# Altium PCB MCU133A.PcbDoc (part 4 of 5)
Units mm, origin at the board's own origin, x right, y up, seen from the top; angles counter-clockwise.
Board outline 58.42 x 139.7 mm, 4 copper layers (Top Signal, GND, PWR, Bottom Signal), stack 1.565 mm thick; 278 components, 226 nets, 1057 pads, 868 vias.
Unrouted connection lines stored in the file: 237.
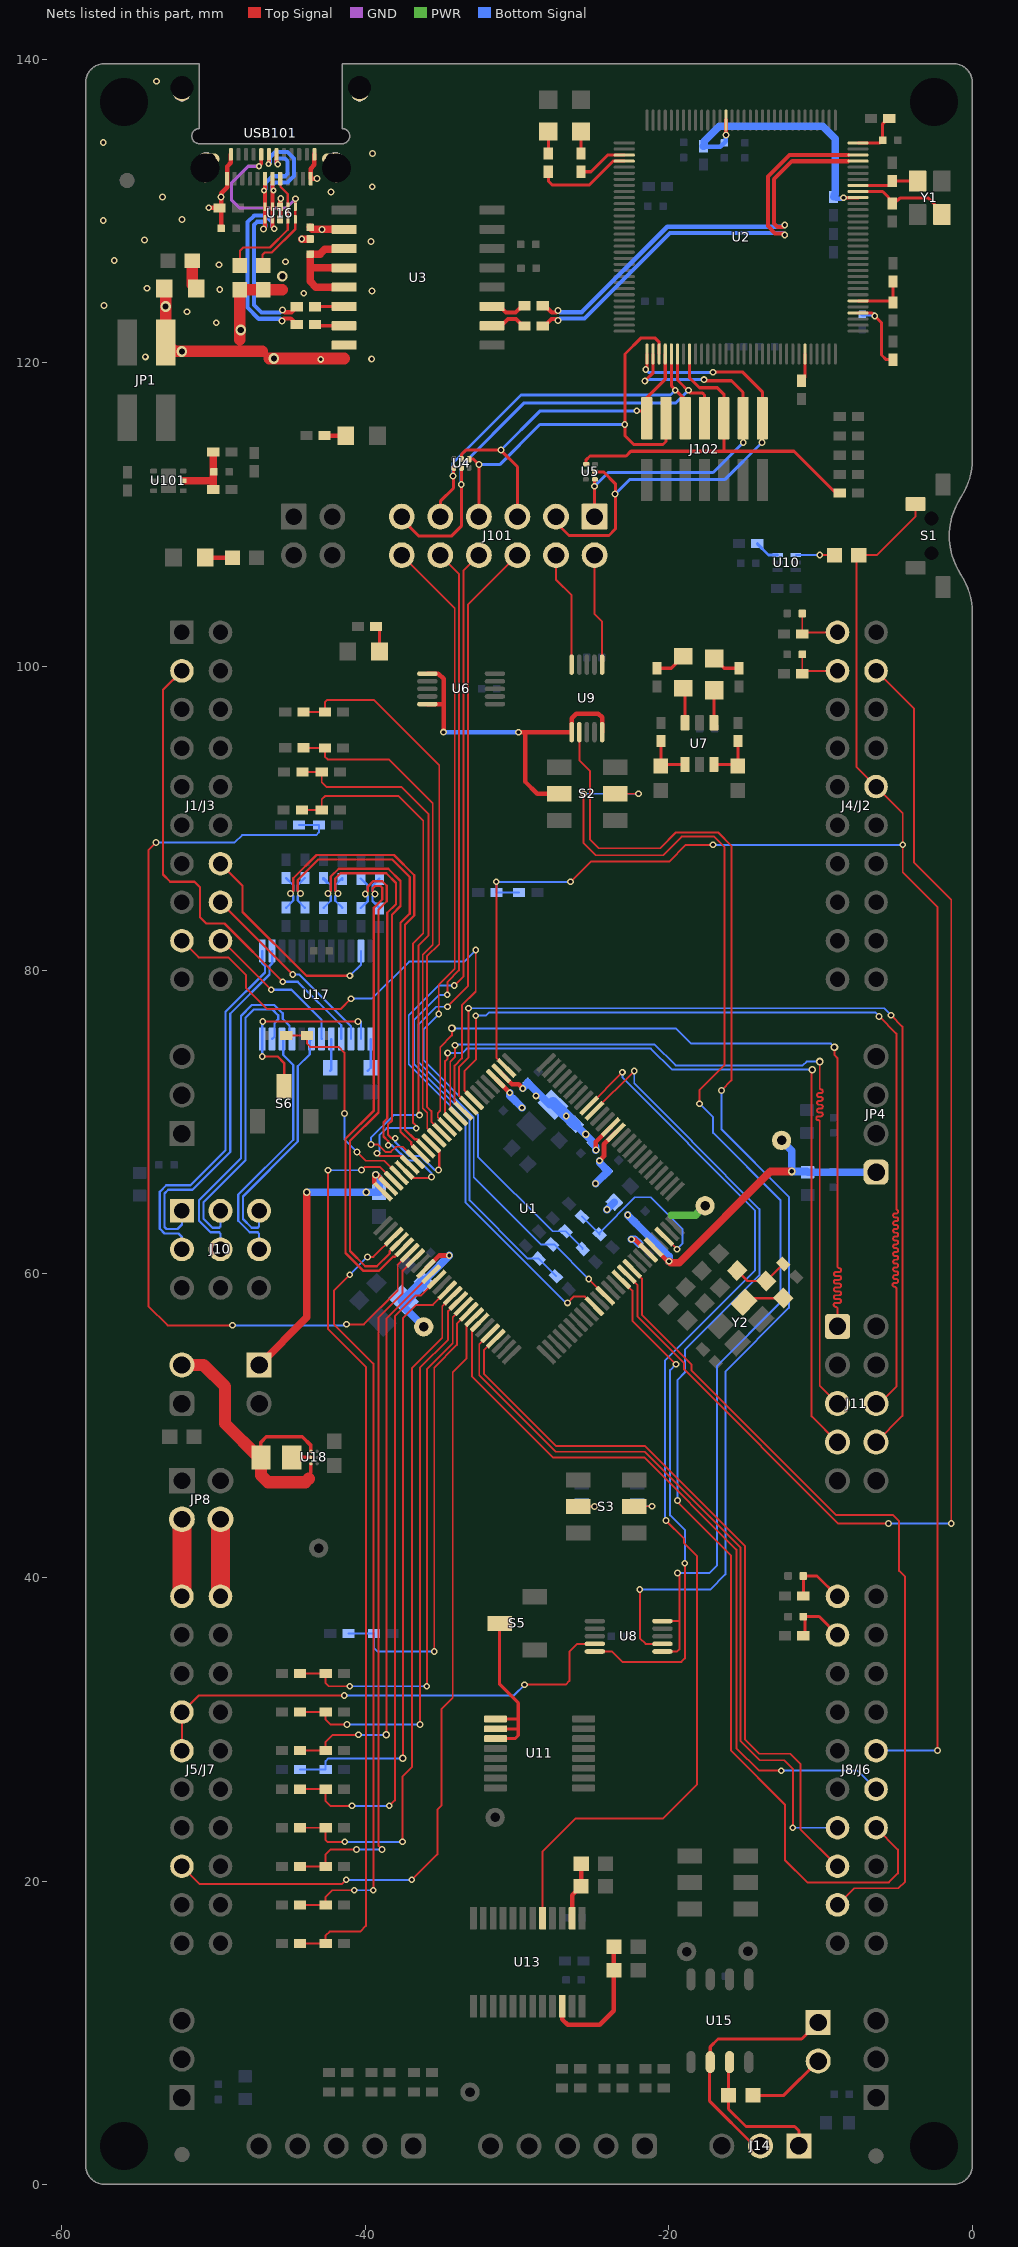
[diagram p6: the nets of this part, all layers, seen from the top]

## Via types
v1: diameter 0.45, hole 0.25, Top Signal to Bottom Signal, tented both sides, 822 vias
v2: diameter 0.5, hole 0.3, Top Signal to Bottom Signal, tented both sides, 22 vias
v3: diameter 0.7, hole 0.4, Top Signal to Bottom Signal, tented both sides, 17 vias
v4: diameter 0.4, hole 0.2, Top Signal to Bottom Signal, tented both sides, 5 vias
v5: diameter 0.5, hole 0.2, Top Signal to Bottom Signal, tented both sides, 2 vias

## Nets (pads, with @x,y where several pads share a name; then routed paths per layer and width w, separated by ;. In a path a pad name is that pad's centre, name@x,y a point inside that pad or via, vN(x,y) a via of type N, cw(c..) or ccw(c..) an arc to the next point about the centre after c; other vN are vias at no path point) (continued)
GPIO49_FSITXD0: J11.6 U1.8 | length 64.1
  Top Signal w0.127: U1.8@-32.818,71.432 -33.447,72.061 -33.447,73.366 -32.715,74.098 v1(-32.715,76.998) ; J11.6@-6.351,51.449 -6.135,51.449 -5.011,52.573 -5.011,59.018 ccw(c-5.138,59.018) -5.138,59.145 cw(c-5.138,59.272) -5.265,59.272 cw(c-5.138,59.272) -5.138,59.399 -5.011,59.399 ccw(c-5.011,59.517) -4.893,59.517 -4.893,59.535 ccw(c-5.011,59.535) -5.011,59.653 -5.1,59.653 cw(c-5.1,59.78) -5.227,59.78 cw(c-5.1,59.78) -5.1,59.907 -5.011,59.907 ccw(c-5.011,60.025) -4.893,60.025 -4.893,60.043 ccw(c-5.011,60.043) -5.011,60.161 -5.1,60.161 cw(c-5.1,60.288) -5.227,60.288 cw(c-5.1,60.288) -5.1,60.415 -5.011,60.415 ccw(c-5.011,60.533) -4.893,60.533 -4.893,60.551 ccw(c-5.011,60.551) -5.011,60.669 -5.1,60.669 cw(c-5.1,60.796) -5.227,60.796 cw(c-5.1,60.796) -5.1,60.923 -5.011,60.923 ccw(c-5.011,61.041) -4.893,61.041 -4.893,61.059 ccw(c-5.011,61.059) -5.011,61.177 -5.1,61.177 cw(c-5.1,61.304) -5.227,61.304 cw(c-5.1,61.304) -5.1,61.431 -5.011,61.431 ccw(c-5.011,61.549) -4.893,61.549 -4.893,61.567 ccw(c-5.011,61.567) -5.011,61.685 -5.1,61.685 cw(c-5.1,61.812) -5.227,61.812 cw(c-5.1,61.812) -5.1,61.939 -5.011,61.939 ccw(c-5.011,62.057) -4.893,62.057 -4.893,62.075 ccw(c-5.011,62.075) -5.011,62.193 -5.1,62.193 cw(c-5.1,62.32) -5.227,62.32 cw(c-5.1,62.32) -5.1,62.447 -5.011,62.447 ccw(c-5.011,62.565) -4.893,62.565 -4.893,62.583 ccw(c-5.011,62.583) -5.011,62.701 -5.1,62.701 cw(c-5.1,62.828) -5.227,62.828 cw(c-5.1,62.828) -5.1,62.955 -5.011,62.955 ccw(c-5.011,63.073) -4.893,63.073 -4.893,63.091 ccw(c-5.011,63.091) -5.011,63.209 -5.1,63.209 cw(c-5.1,63.336) -5.227,63.336 cw(c-5.1,63.336) -5.1,63.463 -5.011,63.463 ccw(c-5.011,63.581) -4.893,63.581 -4.893,63.599 ccw(c-5.011,63.599) -5.011,63.717 -5.1,63.717 cw(c-5.1,63.844) -5.227,63.844 cw(c-5.1,63.844) -5.1,63.971 -5.011,63.971 ccw(c-5.011,64.089) -4.893,64.089 -4.893,64.107 ccw(c-5.011,64.107) -5.011,64.225 -5.011,64.632 -5.011,75.814 v1(-6.148,76.951)
  Bottom Signal w0.127: v1(-32.715,76.998) -32.049,76.998 -31.836,77.211 -6.408,77.211 v1(-6.148,76.951)
GPIO50_FSITXD1: J11.8 U1.9 | length 64.1
  Top Signal w0.127: v1(-33.199,77.488) -33.199,74.232 -33.808,73.622 -33.808,71.715 U1.9@-33.171,71.078 ; J11.8@-6.351,48.909 -4.616,50.644 -4.616,76.282 v1(-5.36,77.027)
  Bottom Signal w0.127: v1(-33.199,77.488) -5.822,77.488 v1(-5.36,77.027)
GPIO51: J1/J3.9 U1.10 | length 34.7
  Top Signal w0.127: J1/J3.9@-52.071,81.929 -50.979,80.837 -49.012,80.837 -47.857,79.682 -47.857,78.833 -46.458,77.433 -41.627,77.433 v1(-40.943,78.117) ; U1.10@-33.525,70.725 -34.116,71.316 -34.116,73.706 -33.637,74.185 -33.637,77.67 -32.716,78.591 v1(-32.716,81.319)
  Bottom Signal w0.127: v1(-40.943,78.117) -39.553,78.117 -37.113,80.557 -33.478,80.557 v1(-32.716,81.319)
GPIO52_FSIRXD0: J11.5 U1.11 | length 55
  Top Signal w0.127: v1(-34.088,75.046) -34.088,74.267 -34.397,73.957 -34.397,70.89 U1.11@-33.878,70.371 ; v2(-10.059,73.979) -10.059,72.245 ccw(c-9.965,72.245) -9.965,72.15 ; -9.986,72.15 cw(c-9.986,72.023) -9.859,72.023 cw(c-9.986,72.023) -9.986,71.896 -10.059,71.896 -10.11,71.896 ccw(c-10.11,71.769) -10.237,71.769 ccw(c-10.11,71.769) -10.11,71.642 -10.059,71.642 -9.986,71.642 cw(c-9.986,71.515) -9.859,71.515 cw(c-9.986,71.515) -9.986,71.388 -10.059,71.388 -10.11,71.388 ccw(c-10.11,71.261) -10.237,71.261 ccw(c-10.11,71.261) -10.11,71.134 -10.059,71.134 -9.986,71.134 cw(c-9.986,71.007) -9.859,71.007 cw(c-9.986,71.007) -9.986,70.88 -10.059,70.88 -10.11,70.88 ccw(c-10.11,70.753) -10.237,70.753 ccw(c-10.11,70.753) -10.11,70.626 -10.059,70.626 -9.986,70.626 cw(c-9.986,70.499) -9.859,70.499 cw(c-9.986,70.499) -9.986,70.372 -10.059,70.372 -10.163,70.372 ccw(c-10.163,70.245) -10.29,70.245 ccw(c-10.163,70.245) -10.163,70.118 cw(c-10.163,70.014) -10.059,70.014 -10.059,69.991 -10.059,52.617 J11.5@-8.891,51.449
  Bottom Signal w0.127: v1(-34.088,75.046) -34.022,75.111 -20.948,75.111 -19.559,73.722 -11.187,73.722 -10.931,73.979 v2(-10.059,73.979)
GPIO53_FSIRXD1: J11.7 U1.12 | length 55
  Top Signal w0.127: v1(-34.568,74.537) -34.568,74.178 -34.743,74.003 -34.743,70.529 -34.568,70.354 U1.12@-34.232,70.018 ; v2(-10.567,73.445) -10.59,73.423 -10.59,50.608 J11.7@-8.891,48.909 J11.7@-9.171,48.909
  Bottom Signal w0.127: v1(-34.568,74.537) -33.614,74.538 -33.317,74.834 -21.18,74.834 -19.791,73.445 v2(-10.567,73.445)
GPIO54_FSIRXCLK: J11.1 U1.13 | length 55
  Top Signal w0.127: U1.13@-34.585,69.664 -35.223,70.302 -35.223,70.587 -35.057,70.753 -35.057,74.925 -34.285,75.697 v2(-34.285,76.163) ; v2(-9.091,74.929) -9.091,74.47 -9.085,74.464 -9.085,74.401 -8.891,74.207 -8.891,60.509 -8.891,60.491 ccw(c-8.764,60.491) -8.764,60.364 ; J11.1@-8.891,56.529 -8.891,57.697 ccw(c-9.018,57.697) -9.018,57.824 cw(c-9.018,57.951) -9.145,57.951 cw(c-9.018,57.951) -9.018,58.078 -8.891,58.078 -8.778,58.078 ccw(c-8.778,58.205) -8.651,58.205 ccw(c-8.778,58.205) -8.778,58.332 -8.891,58.332 -9.004,58.332 cw(c-9.004,58.459) -9.131,58.459 cw(c-9.004,58.459) -9.004,58.586 -8.891,58.586 -8.778,58.586 ccw(c-8.778,58.713) -8.651,58.713 ccw(c-8.778,58.713) -8.778,58.84 -8.891,58.84 -9.004,58.84 cw(c-9.004,58.967) -9.131,58.967 cw(c-9.004,58.967) -9.004,59.094 -8.891,59.094 -8.778,59.094 ccw(c-8.778,59.221) -8.651,59.221 ccw(c-8.778,59.221) -8.778,59.348 -8.891,59.348 -9.004,59.348 cw(c-9.004,59.475) -9.131,59.475 cw(c-9.004,59.475) -9.004,59.602 -8.891,59.602 -8.778,59.602 ccw(c-8.778,59.729) -8.651,59.729 ccw(c-8.778,59.729) -8.778,59.856 -8.891,59.856 -9.004,59.856 cw(c-9.004,59.983) -9.131,59.983 cw(c-9.004,59.983) -9.004,60.11 -8.891,60.11 -8.778,60.11 ccw(c-8.778,60.237) -8.651,60.237 ccw(c-8.778,60.237) -8.778,60.364 ; -8.776,60.364 -8.765,60.364
  Bottom Signal w0.127: v2(-34.285,76.163) -19.538,76.163 -18.535,75.16 -9.322,75.16 v2(-9.091,74.929)
GPIO55: J5/J7.48 U1.43 | length 54.5
  Top Signal w0.127: J5/J7.48@-52.071,20.969 -50.903,19.801 -41.53,19.801 v1(-41.251,20.08) ; v1(-36.933,20.08) -35.251,21.762 -35.251,24.704 -34.963,24.992 -34.963,31.333 -34.231,32.066 -34.231,53.512 -33.329,54.414 -33.329,56.637 U1.43@-32.818,57.148
  Bottom Signal w0.127: v1(-41.251,20.08) v1(-36.933,20.08)
GPIO56: U1.65 U8.10 | length 33.3
  Top Signal w0.127: U8.10@-24.87,35.121 -23.746,35.121 -23.06,34.434 -19.175,34.434 -18.949,34.66 v1(-18.949,40.933) ; U1.65@-23.13,59.623 -22.404,58.897 -22.404,56.91 v1(-19.534,54.04)
  Bottom Signal w0.127: v1(-19.534,54.04) -19.915,53.659 -19.915,44.091 -18.949,43.126 v1(-18.949,40.933)
GPIO56_BP: J5/J7.44 J5/J7.45 U8.9 | length 32.7
  Top Signal w0.127: J5/J7.45@-52.071,28.589 J5/J7.44@-52.071,31.129 -50.979,32.221 v1(-41.378,32.221) ; v1(-29.503,32.932) -26.798,32.932 -26.55,33.181 -26.55,35.098 -26.028,35.621 U8.9@-24.87,35.621
  Bottom Signal w0.127: v1(-41.378,32.221) -30.214,32.221 v1(-29.503,32.932)
GPIO56_SCITX: U8.2 U9.2 | length 80.4
  Top Signal w0.127: U9.2@-25.898,95.674 -25.898,93.825 -25.181,93.108 -25.181,88.595 -24.611,88.025 -20.577,88.025 -19.537,89.065 -16.762,89.065 -15.874,88.177 -15.874,72.735 v1(-16.53,72.08) ; v1(-21.911,39.2) -21.911,35.995 -21.536,35.621 U8.2@-20.42,35.621
  Bottom Signal w0.127: v1(-21.911,39.2) -17.284,39.2 -16.28,40.203 -16.28,53.559 -12.091,57.748 -12.091,65.063 -16.53,69.502 v1(-16.53,72.08)
GPIO57: J4/J2.19 U1.66 | length 87.9
  Top Signal w0.127: U1.66@-22.777,59.977 -22.07,59.269 -22.07,57.196 -18.99,54.116 -18.99,53.703 -8.836,43.55 v1(-5.535,43.55) ; J4/J2.19@-6.351,99.709 -3.844,97.202 -3.844,87.069 -1.398,84.623 v1(-1.398,43.55)
  Bottom Signal w0.127: v1(-5.535,43.55) v1(-1.398,43.55)
GPIO58: J8/J6.72 U1.67 | length 55.1
  Top Signal w0.127: U1.67@-22.423,60.33 -21.771,59.678 -21.771,57.289 -18.501,54.019 -18.501,53.621 -9.001,44.122 -5.248,44.122 -4.83,43.703 -4.83,40.433 -4.441,40.044 -4.441,19.957 -4.873,19.524 -7.796,19.524 J8/J6.72@-8.891,18.429
GPIO59: U1.92 U13.5 | length 73.4
  Top Signal w0.127: U13.5@-28.319,17.602 -28.319,21.95 -26.15,24.119 -20.397,24.119 -18.137,26.379 -18.137,41.391 -19,42.254 -19,42.556 v1(-20.187,43.743) v1@-20.187,43.873 ; U1.92@-25.252,71.078 v1(-23.062,73.268)
  Bottom Signal w0.127: v1(-23.062,73.268) -23.062,72.938 -18.746,68.622 -18.746,68.584 -14.334,64.172 -14.334,60.211 -20.245,54.3 v1@-20.245,43.743
GPIO60: J8/J6.55 U1.44 | length 49.3
  Top Signal w0.127: U1.44@-32.464,56.795 -32.975,56.283 -32.975,53.248 -27.616,47.889 -21.602,47.889 -15.548,41.835 -15.548,28.758 -14.058,27.268 v1(-12.599,27.268)
  Bottom Signal w0.127: v1(-12.599,27.268) -7.57,27.268 J8/J6.55@-6.351,26.049
GPIO61: J8/J6.54 U1.91 | length 76.2
  Top Signal w0.127: U1.91@-24.898,70.725 v1(-22.277,73.346) ; v1@-19.486,45.026 -15.918,41.459 -15.918,28.606 -12.349,25.037 -12.349,21.379 -10.881,19.912 -5.503,19.912 -4.916,20.499 -4.916,22.074 J8/J6.54@-6.351,23.509
  Bottom Signal w0.127: v1(-22.277,73.346) -22.277,72.544 -18.469,68.736 -18.469,68.699 -14.03,64.26 -14.03,59.891 -18.939,54.982 -18.939,53.496 -19.435,53.001 v1(-19.435,45.074) ; v1@-19.489,45.026 v1@-19.489,45.074
GPIO62: J8/J6.74 U1.46 | length 48.8
  Top Signal w0.127: U1.46@-31.757,56.088 -32.488,55.357 -32.488,53.329 -27.433,48.274 -21.576,48.274 -15.271,41.968 -15.271,29.218 -14.007,27.954 -12.396,27.954 -11.836,27.394 -11.836,23.51 v1(-11.837,23.509)
  Bottom Signal w0.127: v1(-11.837,23.509) J8/J6.74@-8.891,23.509
GPIO63: J8/J6.73 U1.47 | length 49.4
  Top Signal w0.127: U1.47@-31.403,55.734 -32.181,54.956 -32.181,53.416 -27.416,48.651 -21.561,48.651 -14.994,42.083 -14.994,29.332 -14.047,28.386 -12.002,28.386 -11.329,27.713 -11.329,23.407 J8/J6.73@-8.891,20.969
MCU_A0/B15/C15/DACA_OUT: C25.1 R12.2 U1.23 | length 60.7
  Top Signal w0.127: R12.2@-44.29,15.889 C25.1@-42.603,15.889 -42.603,16.416 -42.348,16.672 -40.326,16.672 -39.955,17.042 -39.955,53.862 -42.444,56.351 v1(-42.444,66.816) ; v1(-40.245,66.827) -40.042,67.03 -39.023,67.03 U1.23@-38.121,66.128
  Bottom Signal w0.127: v1(-42.444,66.816) -40.256,66.816 v1(-40.245,66.827)
MCU_A1/B7/D11/DACB_OUT: C33.1 R13.2 U1.22 | length 14.9
  Top Signal w0.127: R13.2@-45.202,75.698 C33.1@-43.832,75.698 -43.832,75.149 -43.627,74.944 -41.75,74.944 -41.369,74.563 v1@-41.369,70.552 ; v1(-40.536,68.017) -39.963,67.444 -38.729,67.444 U1.22@-37.767,66.482
  Bottom Signal w0.127: v1@-41.369,70.552 -41.369,68.85 v1(-40.536,68.017)
  other v1: -41.368,70.552
MCU_A4/B8: C27.1 R16.2 U1.36 | length 43
  Top Signal w0.127: R16.2@-44.29,26.049 C27.1@-42.603,26.049 -42.603,25.259 -42.301,24.957 v1(-40.87,24.957) ; v1(-38.411,24.957) -38.05,25.317 -38.05,57.215 -36.703,58.562 -36.353,58.562 U1.36@-35.293,59.623
  Bottom Signal w0.127: v1(-40.87,24.957) v1(-38.411,24.957)
MCU_A5: C35.1 R17.2 U1.35 | length 38
  Top Signal w0.127: R17.2@-44.29,28.589 C35.1@-42.603,28.589 -42.603,29.167 -42.14,29.63 v1(-40.438,29.63) ; v2(-38.609,29.63) -38.609,57.048 -35.68,59.977 U1.35@-35.646,59.977
  Bottom Signal w0.127: v1(-40.438,29.63) v2(-38.609,29.63)
MCU_A6/D14/E14: C28.1 R18.2 U1.14 | length 36.4
  Top Signal w0.127: R18.2@-44.07,96.999 C28.1@-42.654,96.999 -42.654,97.637 -42.492,97.799 -39.442,97.799 -35.121,93.478 -35.121,81.712 -35.934,80.898 -35.934,71.015 -35.634,70.715 -35.634,70.006 U1.14@-34.939,69.31
MCU_A7/B30/C3/D12/E30: C36.1 R19.2 U1.31 | length 64.2
  Top Signal w0.127: v1(-53.773,88.406) -54.281,87.898 -54.281,57.875 -53.011,56.605 v1(-48.744,56.605) ; v1(-41.225,56.669) -40.082,56.669 -37.854,58.897 -37.854,60.597 U1.31@-37.06,61.391
  Bottom Signal w0.127: v1(-53.773,88.406) -48.591,88.406 -48.105,88.892 -43.231,88.892 -43.054,89.069 C36.1@-43.054,89.549 R19.2@-44.354,89.549 ; v1(-48.744,56.605) -41.289,56.605 v1(-41.225,56.669)
MCU_A9: C29.1 R20.2 U1.38 | length 40.1
  Top Signal w0.127: v2(-37.517,28.081) -37.517,57.071 -36.633,57.954 -35.547,57.954 U1.38@-34.585,58.916
  Bottom Signal w0.127: R20.2@-44.29,27.344 C29.1@-42.603,27.344 -42.603,27.897 -42.419,28.081 v2(-37.517,28.081)
MCU_A10/B1/C10: C37.1 R21.2 U1.40 | length 37.5
  Top Signal w0.127: R21.2@-44.29,31.129 C37.1@-42.603,31.129 -42.603,30.627 -42.292,30.316 v1(-41.2,30.316) ; v1(-36.399,30.316) -36.399,53.813 -34.545,55.667 -34.545,57.542 U1.40@-33.878,58.209
  Bottom Signal w0.127: v1(-41.2,30.316) v1(-36.399,30.316)
MCU_A11/B10/C0/PGA2_OUT: C30.1 R22.2 U1.20 | length 36.1
  Top Signal w0.127: R22.2@-44.028,90.549 C30.1@-42.861,90.549 -42.861,91.25 -42.648,91.463 -37.796,91.463 -36.176,89.843 -36.176,82.418 -36.854,81.74 -36.854,69.963 v1@-36.638,69.747 ; v1(-39.219,67.934) -39.034,67.749 -37.62,67.749 U1.20@-37.06,67.189
  Bottom Signal w0.127: v1(-39.219,67.934) -39.061,68.092 -39.061,69.117 -38.588,69.589 v1(-36.638,69.589)
MCU_A12/C5: C38.1 R23.2 U1.28 | length 51.5
  Top Signal w0.127: R23.2@-44.29,18.429 C38.1@-42.603,18.429 -42.603,18.961 -42.17,19.394 v1(-40.717,19.394) ; v1(-41.022,59.935) -42.063,58.894 -42.063,56.681 -39.465,54.083 v1(-39.465,19.394) ; v1(-39.854,61.108) -39.465,61.108 U1.28@-38.121,62.451
  Bottom Signal w0.127: v1(-41.022,59.935) -41.022,59.94 v1(-39.854,61.108) ; v1(-40.717,19.394) v1(-39.465,19.394)
MCU_A14/B14/C4/PGA1_OUT: C31.1 R24.2 U1.19 | length 37.8
  Top Signal w0.127: R24.2@-44.137,93.039 C31.1@-42.861,93.039 -42.861,92.375 -42.538,92.052 -37.603,92.052 -35.826,90.275 -35.826,82.296 -36.488,81.634 -36.488,70.519 v1(-36.416,70.447) ; v1(-39.625,68.518) -39.158,68.518 -38.666,68.026 -38.303,68.026 -37.963,68.366 -37.53,68.366 U1.19@-36.707,67.543
  Bottom Signal w0.127: v1(-39.625,68.518) -39.625,68.944 -38.123,70.447 v1(-36.416,70.447)
MCU_B0/C11: C107.1 R109.2 U1.41 | length 35.1
  Top Signal w0.127: C107.1@-42.603,33.669 -42.603,33.031 -42.403,32.831 v1(-41.022,32.831) ; v1(-35.942,32.831) -35.942,53.724 -34.235,55.431 -34.235,57.145 U1.41@-33.525,57.855
  Top Signal w0.15: R109.2@-44.29,33.669 C107.1@-42.603,33.669
  Bottom Signal w0.127: v1(-41.022,32.831) v1(-35.942,32.831)
MCU_B2/C6/E12: C39.1 R25.2 U1.15 | length 33
  Top Signal w0.127: R25.2@-44.064,94.645 -44.048,94.629 C39.1@-42.656,94.629 -42.656,94.054 -42.478,93.877 -38.448,93.877 -35.549,90.977 -35.549,81.675 -36.211,81.013 -36.211,70.901 -35.911,70.6 -35.911,69.576 U1.15@-35.293,68.957
MCU_B4/C8: C40.1 R27.2 U1.39 | length 45
  Top Signal w0.127: R27.2@-44.29,23.509 C40.1@-42.603,23.509 -42.603,22.702 -42.486,22.585 v1(-41.352,22.585) ; v1(-37.538,22.585) -37.538,26.891 -36.907,27.522 -36.907,53.798 -34.926,55.779 -34.926,57.868 U1.39@-34.232,58.562
  Bottom Signal w0.127: v1(-41.352,22.585) v1(-37.538,22.585)
MCU_B5/D15/E15/PGA3_OUT: C75.1 R84.2 U1.32 | length 46.4
  Top Signal w0.127: R84.2@-44.29,20.969 C75.1@-42.603,20.969 -42.603,21.76 -42.276,22.087 v1(-40.565,22.087) ; v1(-38.888,22.087) -39.117,22.315 -39.117,23.331 -39.117,56.732 -39.117,57.123 -37.536,58.704 -37.536,60.208 U1.32@-36.707,61.037
  Bottom Signal w0.127: v1(-40.565,22.087) v1(-38.888,22.087)
MCU_C14: C108.1 R110.2 U1.42 | length 30
  Top Signal w0.127: v1(-35.452,35.11) -35.452,53.816 -33.958,55.309 -33.958,56.714 U1.42@-33.171,57.502
  Bottom Signal w0.127: C108.1@-39.415,36.304 -39.415,35.349 -39.177,35.11 v1(-35.452,35.11)
  Bottom Signal w0.15: R110.2@-41.102,36.304 C108.1@-39.415,36.304
MCU_PGA1_IN_N: C34.1 R15.2 U1.18 | length 30.9
  Top Signal w0.15: v1(-44.265,85.05) -44.44,85.225 -44.44,85.928 -43.089,87.279 -38.22,87.279 -37.066,86.125 -37.066,83.721 -37.671,83.116 -37.671,69.355 -36.972,68.656 -36.972,68.515 U1.18@-36.353,67.896
  Bottom Signal w0.15: C34.1@-43.976,86.068 -44.44,85.604 -44.44,85.225 v1(-44.265,85.05) -44.44,84.875 -44.44,84.58 R15.2@-43.974,84.115
MCU_PGA1_IN_P: C26.1 R14.2 U1.17 | length 31.6
  Top Signal w0.15: v1(-44.915,85.05) -44.74,85.225 -44.74,86.052 -43.213,87.579 -38.096,87.579 -36.766,86.249 -36.766,83.597 -37.371,82.992 -37.371,69.48 -36.76,68.868 -36.618,68.868 U1.17@-36,68.25
  Bottom Signal w0.15: C26.1@-45.211,86.066 -44.74,85.596 -44.74,85.225 v1(-44.915,85.05) -44.74,84.875 -44.74,84.58 R14.2@-45.206,84.115
MCU_PGA2_IN_N: C76.1 R86.2 U1.21 | length 31.6
  Top Signal w0.15: v1(-41.793,85.043) -41.968,85.218 -41.968,86.037 -41.622,86.384 -38.612,86.384 -37.968,85.74 -37.968,84.343 -38.541,83.771 -38.541,70.223 -38.796,69.968 -38.796,69.036 -38.484,68.724 v1(-38.484,68.465) ; U1.21@-37.414,66.836 -36.891,66.313 -35.693,66.313 v1(-35.638,66.368)
  Bottom Signal w0.15: C76.1@-41.512,85.951 C76.1@-41.512,86.005 ; C76.1@-41.504,86.062 -41.968,85.597 -41.968,85.218 v1(-41.793,85.043) -41.968,84.868 -41.968,84.574 R86.2@-41.503,84.108 ; v1(-38.484,68.465) -38.233,68.465 -37.221,67.453 -36.475,67.453 -35.638,66.615 v1(-35.638,66.368)
MCU_PGA2_IN_P: C32.1 R26.2 U1.16 | length 32.7
  Top Signal w0.15: v1(-42.443,85.043) -42.268,85.218 -42.268,86.161 -41.746,86.684 -38.488,86.684 -37.668,85.864 -37.668,84.219 -38.241,83.647 -38.241,70.099 -38.496,69.844 -38.496,69.16 -38.26,68.924 v1(-38.025,68.924) ; U1.16@-35.646,68.603 -35.123,68.081 -35.123,66.882 v1(-35.178,66.827)
  Bottom Signal w0.15: C32.1@-42.755,86.064 -42.755,85.986 C32.1@-42.53,85.761 ; C32.1@-42.739,86.059 -42.268,85.589 -42.268,85.218 v1(-42.443,85.043) -42.268,84.868 -42.268,84.574 R26.2@-42.734,84.108 ; v1(-38.025,68.924) -38.025,68.68 -37.097,67.753 -36.351,67.753 -35.426,66.827 v1(-35.178,66.827)
MCU_PGA3_IN_N: C77.1 R85.2 U1.30 | length 33.8
  Top Signal w0.15: v1(-39.348,85.02) -39.523,85.195 -39.523,85.38 -39.357,85.547 -38.993,85.547 -38.873,85.427 -38.873,84.656 -39.428,84.101 -39.428,70.753 -41.297,68.885 -41.297,61.37 -40.116,60.189 -39.11,60.189 -38.174,61.126 -38.033,61.126 U1.30@-37.414,61.744
  Bottom Signal w0.15: C77.1@-39.059,86.038 -39.523,85.574 -39.523,85.195 v1(-39.348,85.02) -39.523,84.845 -39.523,84.551 R85.2@-39.057,84.085
MCU_PGA3_IN_P: C78.1 R87.2 U1.29 | length 34
  Top Signal w0.15: v1(-39.998,85.02) -39.823,85.195 -39.823,85.504 -39.481,85.847 -38.869,85.847 -38.573,85.551 -38.573,84.532 -39.128,83.977 -39.128,70.629 -40.997,68.761 -40.997,61.494 -39.992,60.489 -39.235,60.489 -38.386,61.338 -38.386,61.479 U1.29@-37.767,62.098
  Bottom Signal w0.15: C78.1@-40.294,86.036 -39.823,85.566 -39.823,85.195 v1(-39.998,85.02) -39.823,84.845 -39.823,84.551 R87.2@-40.289,84.085
MCU_RXD: J101.2 U9.6 | length 7.4
  Top Signal w0.127: J101.2@-24.893,107.329 -24.893,103.443 -24.398,102.948 U9.6@-24.398,100.124
MCU_TCK: J101.8 U1.60 | length 58.4
  Top Signal w0.127: v1(-34.139,78.983) -33.513,79.608 -33.513,106.329 J101.8@-32.513,107.329 ; v1(-26.671,58.084) -26.671,58.1 -26.28,58.492 -25.535,58.492 U1.60@-24.898,57.855
  Bottom Signal w0.127: v1(-34.139,78.983) -35.18,78.983 -37.131,77.032 -37.131,73.789 -33.404,70.063 -33.404,64.712 -26.776,58.084 v1(-26.671,58.084)
MCU_TDI: J101.12 R44.2 R111.1 | length 52.8
  Top Signal w0.127: J101.12@-37.593,107.329 -34.101,103.837 -34.101,80.099 -35.155,79.045 v1(-35.155,77.103)
  Bottom Signal w0.127: v1(-35.155,77.103) -36.159,76.099 -36.159,74.062 -32.573,70.477 -32.573,67.719 -27.657,62.802 R111.1@-26.798,62.802 -25.676,61.68 R44.2@-25.676,61.63
MCU_TDO: J101.10 R45.2 R112.1 | length 53.8
  Top Signal w0.127: J101.10@-35.053,107.329 -33.824,106.1 -33.824,79.984 -34.577,79.231 -34.577,78.392 v1(-34.596,78.373)
  Bottom Signal w0.127: v1(-34.596,78.373) -35.129,78.373 -36.79,76.712 -36.79,73.84 -33.127,70.177 -33.127,64.827 -29.299,60.998 R112.1@-28.573,60.998 -27.443,59.868 R45.2@-27.443,59.835
MCU_TMS: J101.6 R10.1 U1.62 | length 57.5
  Top Signal w0.127: v1(-34.585,77.586) -33.236,78.935 -33.236,104.066 J101.6@-29.973,107.329 ; v1(-25.274,59.645) U1.62@-24.191,58.562
  Bottom Signal w0.127: v1(-34.585,77.586) -35.332,77.586 -36.475,76.443 -36.475,73.917 -32.85,70.292 -32.85,66.358 -28.425,61.933 R10.1@-27.698,61.933 -27.556,61.933 -25.274,59.65 v1(-25.274,59.645)
MCU_TXD: J101.4 U9.10 | length 7.6
  Top Signal w0.127: J101.4@-27.433,107.329 -27.433,105.729 -26.398,104.694 U9.10@-26.398,100.124
MCU_VREFHI: C24.1 J15.1 U1.24 U1.25 | length 21.3
  Top Signal w0.3: U1.25@-38.828,65.421 -39.418,66.011 -39.418,66.511 v2(-39.314,66.511) -39.211,66.511 U1.24@-38.475,65.775
  Top Signal w0.5: J15.1@-46.991,53.989 -43.854,57.126 v2(-43.854,65.369)
  Bottom Signal w0.5: v2(-43.854,65.369) v2(-39.94,65.369) C24.1@-39.092,65.369 -39.092,66.288 v2(-39.314,66.511)
NetC7_1: C7.1 U10.3 | length 1.6
  Bottom Signal w0.2: C7.1@-14.174,108.091 -13.43,107.346 U10.3@-12.836,107.346
NetC50_2: C50.2 R62.2 U2.96 | length 3.5
  Top Signal w0.2: U2.96@-7.536,134.484 -6.095,134.484 C50.2@-5.914,134.665 -5.914,135.743 -5.665,135.992 R62.2@-5.302,135.992
NetC59_1: C59.1 C60.2 C61.1 U2.87 U2.115 | length 18.3
  Top Signal w0.254: v1(-16.236,135.002) U2.115@-16.236,135.984 ; v1(-8.503,130.869) U2.87@-7.521,130.869
  Bottom Signal w0.3: C61.1@-17.715,134.267 -17.672,134.225 -17.241,134.225 -16.609,134.225 -16.237,134.597 -16.237,134.896 -16.236,134.897 v1(-16.236,135.002) ; C59.1@-9.144,130.923 -9.021,130.8 -8.613,130.8 -8.559,130.853 v1@-8.519,130.853
  Bottom Signal w0.5: C61.1@-17.715,134.267 -17.665,134.317 -17.665,134.596 -16.666,135.595 -9.878,135.595 -9.052,134.769 -9.052,131.115 -9.094,131.073 -9.094,130.973 C59.1@-9.119,130.948
NetC62_1: C62.1 U2.88 Y1.1 | length 6.6
  Top Signal w0.2: U2.88@-7.536,131.284 -5.916,131.284 -5.132,130.5 -4.782,130.849 -2.89,130.849 Y1.1@-1.817,129.776
NetC63_1: C63.1 U2.89 Y1.3 | length 4.2
  Top Signal w0.2: U2.89@-7.536,131.684 -5.424,131.684 -5.132,131.976 Y1.3@-3.417,131.976
NetC66_2: C66.2 R70.1 U2.68 | length 5.7
  Top Signal w0.2: U2.68@-7.536,123.284 -6.63,123.284 -5.992,122.646 -5.992,120.512 -5.686,120.206 R70.1@-5.242,120.206
  Bottom Signal w0.3: C66.2@-7.252,123.197 -6.548,123.197 v1(-6.44,123.089)
NetC81_2: C81.2 J8/J6.79 R50.2 | length 4.1
  Top Signal w0.2: R50.2@-11.149,36.157 -11.046,36.26 -11.046,37.316 C81.2@-11.149,37.419 -10.101,37.419 J8/J6.79@-8.891,36.209
NetC82_2: C82.2 J8/J6.80 R49.2 | length 4.2
  Top Signal w0.127: R49.2@-11.12,38.895 R49.2@-10.974,38.749
  Top Signal w0.2: C82.2@-11.148,40.094 C82.2@-11.12,40.094 ; R49.2@-11.12,38.895 C82.2@-11.12,40.094 ; J8/J6.80@-8.891,38.749 -10.236,40.094 C82.2@-11.12,40.094
NetC83_2: C83.2 J4/J2.39 R9.2 | length 3.9
  Top Signal w0.127: C83.2@-11.21,100.798 -11.213,100.795 R9.2@-11.213,99.524 -11.028,99.709 J4/J2.39@-8.891,99.709 J4/J2.39@-9.076,99.524
NetC84_2: C84.2 J4/J2.40 R8.2 | length 3.7
  Top Signal w0.127: C84.2@-11.21,103.492 -11.213,103.489 R8.2@-11.213,102.134 -11.098,102.249 -9.006,102.249 J4/J2.40@-8.948,102.192
NetC102_1: C102.1 R101.1 R102.2 U101.2 | length 4.4
  Top Signal w0.508: U101.2@-51.985,112.224 -50.053,112.224 ; R101.1@-50.004,111.647 R102.2@-50.004,114.136
NetC106_2: C106.2 U3.3 U3.4 U3.5 | length 8.8
  Top Signal w0.5: U3.5@-41.39,124.982 -43.248,124.982 -43.627,125.361 -43.627,126.268 ; U3.4@-41.39,126.252 -43.611,126.252 -43.627,126.268 ; U3.3@-41.39,127.522 -41.39,127.479 -42.657,127.479 -42.979,127.157 C106.2@-43.627,127.157 -43.627,126.268
NetJ5/J7_41: J5/J7.41 JP8.3 | length 5.1
  Top Signal w1.27: J5/J7.41@-52.071,38.749 JP8.3@-52.071,43.829
NetJ5/J7_61: J5/J7.61 JP8.4 | length 5.1
  Top Signal w1.27: J5/J7.61@-49.531,38.749 JP8.4@-49.531,43.829
NetJ14_1: J14.1 R79.2 U15.7 | length 9.3
  Top Signal w0.2: U15.7@-16.064,8.076 -16.064,5.881 -16.064,4.977 -14.922,3.835 -11.715,3.835 -11.431,3.551 J14.1@-11.431,2.554
NetJ14_2: J14.2 JP9.1 U15.6 | length 16.1
  Top Signal w0.2: U15.6@-17.334,8.269 -17.334,8.076 -17.334,5.536 -14.352,2.554 J14.2@-13.971,2.554 ; U15.6@-17.273,8.076 -17.273,8.269 -17.273,9.082 -16.765,9.59 -11.253,9.59 JP9.1@-10.161,10.682
NetJ16_2: J16.2 L4.1 U18.A1 U18.C1 | length 19.3
  Top Signal w0.23: L4.1@-46.864,47.893 -46.864,48.914 -46.513,49.265 -44.146,49.265 -43.571,48.689 U18.A1@-43.571,48.298 ; -43.571,46.919 U18.C1@-43.571,47.498
  Top Signal w0.8: J16.2@-52.071,53.989 -50.649,53.989 -49.226,52.567 -49.226,50.128 L4.1@-46.991,47.893 ; L4.1@-46.864,47.893 -46.864,46.725 -46.407,46.267 -43.943,46.267 -43.714,46.496
NetJP9_2: JP9.2 R79.1 | length 5.2
  Top Signal w0.2: R79.1@-14.466,5.881 -12.422,5.881 JP9.2@-10.161,8.142
NetL4_2: L4.2 U18.B1 | length 1.3
  Top Signal w0.23: L4.2@-44.827,47.898 U18.B1@-43.571,47.898
NetLED0_2: LED0.2 R105.1 | length 1.4
  Top Signal w0.3: R105.1@-42.673,115.203 LED0.2@-41.285,115.203
NetLED1_2: LED1.2 R3.1 | length 1.8
  Top Signal w0.203: R3.1@-39.285,102.645 -39.057,102.417 LED1.2@-39.057,100.979
NetLED2_1: LED2.1 R63.1 | length 1.4
  Top Signal w0.2: R63.1@-25.782,133.786 LED2.1@-25.782,135.235
NetLED3_1: LED3.1 R64.1 | length 1.4
  Top Signal w0.2: R64.1@-27.941,133.786 LED3.1@-27.941,135.235
NetLED4_1: LED4.1 U7.6 | length 2.3
  Top Signal w0.203: LED4.1@-19.051,98.566 -18.933,98.448 U7.6@-18.933,96.297
NetLED4_2: LED4.2 R28.1 | length 2.1
  Top Signal w0.203: R28.1@-20.782,99.885 -19.832,99.885 LED4.2@-19.051,100.666
NetLED5_1: LED5.1 R29.1 | length 1.9
  Top Signal w0.203: LED5.1@-17.003,100.528 -16.36,99.885 R29.1@-15.368,99.885
NetLED5_2: LED5.2 U7.4 | length 2.1
  Top Signal w0.203: U7.4@-17.033,96.297 -17.033,98.323 LED5.2@-16.967,98.389
NetLED6_2: LED6.2 R43.1 | length 1.8
  Top Signal w0.3: LED6.2@-50.526,107.171 R43.1@-48.75,107.171
NetLED7_2: LED7.2 R7.1 | length 1.9
  Top Signal w0.762: R7.1@-51.393,126.718 -51.393,125.148 LED7.2@-51.135,124.89
NetR1_1: R1.1 U3.11 | length 2.4
  Top Signal w0.27: U3.11@-31.64,123.712 -31.135,123.712 -30.725,123.303 -30.092,123.303 R1.1@-29.636,123.759
NetR2_1: R2.1 U3.10 | length 2.4
  Top Signal w0.27: U3.10@-31.685,122.514 -30.955,122.514 -30.586,122.883 -30.074,122.883 R2.1@-29.618,122.426
NetR5_2: R5.2 U10.4 | length 2.6
  Top Signal w0.127: v1(-10.059,107.346) -9.103,107.346 R5.2@-9.086,107.329
  Bottom Signal w0.127: U10.4@-11.636,107.346 v1(-10.059,107.346)
NetR30_1: R30.1 R34.2 U7.1 | length 3.3
  Top Signal w0.203: R30.1@-20.523,95.084 R34.2@-20.523,93.436 -20.412,93.547 U7.1@-18.933,93.547
NetR31_1: R31.1 R35.2 U7.3 | length 3.3
  Top Signal w0.203: U7.3@-17.033,93.547 -15.58,93.547 R35.2@-15.469,93.436 -15.443,93.461 R31.1@-15.443,95.084
NetR38_2: R38.2 S3.5 | length 2.3
  Top Signal w0.127: S3.5@-25.974,44.666 -25.97,44.67 v1(-24.889,44.67)
  Bottom Signal w0.127: R38.2@-26.094,44.697 -26.067,44.67 v1(-24.889,44.67)
NetR39_1: R39.1 S3.2 | length 2.1
  Top Signal w0.127: S3.2@-22.274,44.666 -22.252,44.688 v1(-21.11,44.688)
  Bottom Signal w0.127: R39.1@-22.068,44.697 -22.059,44.688 v1(-21.11,44.688)
NetR47_1: R47.1 R52.2 U13.2 | length 3.8
  Top Signal w0.3: U13.2@-26.369,17.602 -26.369,19.077 R47.1@-25.779,19.667 -25.779,21.115 R52.2@-25.766,21.128
NetR48_1: R48.1 R53.1 U13.22 | length 9
  Top Signal w0.3: U13.22@-27.019,11.702 -27.019,10.884 -26.67,10.535 -24.549,10.535 -23.617,11.467 R53.1@-23.617,14.111 R48.1@-23.617,15.762
NetR63_2: R63.2 U2.3 | length 3.3
  Top Signal w0.2: R63.2@-25.782,132.586 -25.125,132.586 -24.027,133.684 U2.3@-22.936,133.684
NetR64_2: R64.2 U2.4 | length 6.4
  Top Signal w0.2: R64.2@-27.941,132.586 -27.941,131.98 -27.663,131.702 -25.261,131.702 -23.679,133.284 U2.4@-22.936,133.284
NetR65_1: R65.1 R67.2 U2.70 | length 3.7
  Top Signal w0.2: U2.70@-7.536,124.084 -5.333,124.084 R65.1@-5.233,123.984 R67.2@-5.233,125.363
NetR68_2: R68.2 U2.59 | length 1.9
  Top Signal w0.2: R68.2@-11.263,118.823 -11.036,119.05 U2.59@-11.036,120.584
NetR82_2: R82.2 R83.1 U1.73 | length 11.7
  Top Signal w0.127: U1.73@-20.302,62.451 -19.459,61.609 v1(-19.457,61.609)
  Bottom Signal w0.127: R82.2@-25.719,63.76 -25.719,63.756 R83.1@-24.56,62.596 -24.56,62.711 -22.233,65.038 -21.208,65.038 -19.096,62.926 -19.096,62.021 -19.457,61.66 v1(-19.457,61.609)
NetR103_2: R103.2 U3.6 | length 1.9
  Top Signal w0.2: R103.2@-43.306,123.692 -43.286,123.712 U3.6@-41.39,123.712
NetR104_2: R104.2 U3.7 | length 1.9
  Top Signal w0.2: R104.2@-43.306,122.515 -43.233,122.442 U3.7@-41.39,122.442
NetR106_1: R106.1 Y2.3 | length 2.7
  Top Signal w0.152: Y2.3@-15.049,58.122 -14.774,58.396 R106.1@-12.459,58.396
PGA1_IN_N: J10.4 U17.1 | length 24.7
  Bottom Signal w0.15: J10.4@-52.071,61.609 -52.071,62.427 -52.3,62.655 -53.217,62.655 -53.523,62.962 -53.523,65.408 -53.098,65.834 -51.501,65.834 -49.196,68.139 -49.196,77.253 -46.606,79.843 -46.606,80.263 -46.781,80.438 U17.1@-46.781,81.263
PGA1_IN_N_BP: R107.1 U17.13 | length 2.2
  Bottom Signal w0.15: R107.1@-39.823,73.376 R107.1@-39.631,73.569 U17.13@-39.631,75.463
PGA1_IN_P: J10.1 U17.2 | length 24.3
  Bottom Signal w0.15: J10.1@-52.071,64.149 -52.071,63.252 -52.368,62.955 -53.093,62.955 -53.223,63.086 -53.223,65.284 -52.973,65.534 -51.377,65.534 -48.896,68.015 -48.896,77.128 -46.306,79.719 -46.306,80.263 -46.131,80.438 U17.2@-46.131,81.263
PGA1_IN_P_BP: J1/J3.27 U17.11 | length 14.5
  Top Signal w0.15: J1/J3.27@-49.531,87.009 -48.083,85.561 -48.083,83.835 -43.872,79.624 v1(-41.011,79.624)
  Bottom Signal w0.15: v1(-41.011,79.624) -40.281,80.354 U17.11@-40.281,81.263
PGA2_IN_N: J10.5 U17.21 | length 22.7
  Bottom Signal w0.15: J10.5@-49.531,61.609 -49.531,62.641 -49.619,62.729 -50.188,62.729 -50.951,63.492 -50.951,64.836 -48.18,67.607 -48.18,76.985 -47.466,77.699 -45.984,77.699 -45.436,77.151 -45.436,76.793 -44.981,76.337 -44.981,75.613 U17.21@-44.831,75.463
PGA2_IN_N_BP: R108.1 U17.17 | length 2.1
  Bottom Signal w0.15: R108.1@-42.296,73.376 -42.231,73.441 U17.17@-42.231,75.463
PGA2_IN_P: J10.2 U17.23 | length 21.1
  Bottom Signal w0.15: J10.2@-49.531,64.149 -49.531,63.117 -49.619,63.029 -50.063,63.029 -50.651,63.617 -50.651,64.712 -47.88,67.483 -47.88,76.861 -47.342,77.399 -46.109,77.399 -45.736,77.026 -45.736,76.748 -45.981,76.504 -45.981,75.613 U17.23@-46.131,75.463
PGA2_IN_P_BP: J1/J3.28 U17.15 | length 12.8
  Top Signal w0.15: J1/J3.28@-49.531,84.469 v1(-44.77,79.708)
  Bottom Signal w0.15: v1(-44.77,79.708) -44.338,79.708 -40.931,76.3 U17.15@-40.931,75.463
PGA3_IN_N: J10.6 U17.22 | length 16.5
  Bottom Signal w0.15: J10.6@-46.991,61.609 -46.991,62.641 -47.079,62.729 -47.598,62.729 -48.356,63.487 -48.356,65.217 -44.74,68.833 -44.74,73.753 -45.401,74.414 -45.401,75.383 U17.22@-45.481,75.463
PGA3_IN_N_BP: J1/J3.2 U17.16 | length 31.8
  Top Signal w0.15: J1/J3.2@-52.071,99.709 -53.316,98.464 -53.316,86.298 -52.833,85.815 -51.237,85.815 -50.877,85.456 -50.877,83.478 -50.471,83.072 -49.26,83.072 -45.429,79.241 v1(-45.429,79.237)
  Bottom Signal w0.15: v1(-45.429,79.237) -44.451,79.237 -41.581,76.366 U17.16@-41.581,75.463
PGA3_IN_P: J10.3 U17.19 | length 16.1
  Bottom Signal w0.15: J10.3@-46.991,64.149 -46.991,63.117 -47.079,63.029 -47.473,63.029 -48.056,63.612 -48.056,65.093 -44.44,68.709 -44.44,73.669 -43.658,74.45 -43.658,75.335 U17.19@-43.531,75.463
PGA3_IN_P_BP: J1/J3.29 U17.18 | length 10.1
  Top Signal w0.15: J1/J3.29@-49.531,81.929 -49.417,81.929 v1(-46.191,78.703)
  Bottom Signal w0.15: v1(-46.191,78.703) -44.857,78.703 -42.881,76.726 U17.18@-42.881,75.463 U17.18@-42.863,75.48
PGA_SEL: S6.2 U17.14 U17.24 | length 12.9
  Top Signal w0.15: v1(-46.781,74.309) -45.762,74.309 -45.34,73.887 S6.2@-45.34,72.353 ; v1(-46.75,76.62) v1(-40.471,76.622)
  Bottom Signal w0.15: v1(-46.781,74.309) U17.24@-46.781,75.463 -46.781,76.589 v1(-46.75,76.62) ; U17.14@-40.281,75.463 v1@-40.281,76.62
QEP3_SEL: S5.2 U11.9 U11.10 U11.11 | length 12.5
  Top Signal w0.2: U11.11@-31.413,29.379 -30.13,29.379 -29.919,29.59 -29.919,30.029 ; U11.10@-31.413,30.029 -29.919,30.029 ; U11.9@-31.413,30.679 -29.919,30.679 ; S5.2@-31.164,36.972 -31.164,32.985 -29.919,31.74 -29.919,30.679 ; -29.919,30.029 -29.919,30.679
SCI_SEL1: S2.2 U6.1 U6.5 U9.1 U9.5 | length 24.2
  Top Signal w0.3: U6.5@-35.904,97.523 -34.882,97.523 -34.839,97.48 ; U6.1@-35.904,99.523 -35.178,99.523 -34.836,99.181 v1(-34.836,95.674) ; v1(-29.912,95.67) -29.908,95.674 -29.47,95.674 ; S2.2@-27.224,91.615 -28.663,91.615 -29.47,92.421 -29.47,95.674 ; U9.5@-24.398,95.674 -24.398,96.649 -24.639,96.89 -26.09,96.89 -26.398,96.581 U9.1@-26.398,95.674 -29.47,95.674
  Bottom Signal w0.3: v1(-34.836,95.674) -34.833,95.67 v1(-29.912,95.67)
SCI_SEL2: S2.5 U8.1 U8.5 | length 80.9
  Top Signal w0.127: v1(-25.619,91.615) -25.613,91.609 -25.613,88.355 -24.826,87.568 -20.379,87.568 -19.159,88.788 -17.01,88.788 -16.326,88.104 -16.326,73.768 -17.976,72.118 v1(-17.976,71.194) ; S2.5@-23.524,91.615 v1(-21.999,91.615) ; U8.1@-20.42,35.121 -19.448,35.121 -19.309,35.26 -19.309,37.12 ; U8.5@-20.42,37.121 -19.309,37.121 ; v1(-19.432,40.298) -19.309,40.175 -19.309,37.121
  Bottom Signal w0.127: v1(-25.619,91.615) v1(-21.999,91.615) ; v1(-19.432,40.298) -17.313,40.298 -16.834,40.777 -16.834,53.92 -12.645,58.109 -12.645,64.834 -17.084,69.272 -17.084,70.302 v1(-17.976,71.194)
USB_CC1: R88.2 U16.4 U16.7 USB101.A5 | length 8.1
  Top Signal w0.152: R88.2@-48.251,126.414 -48.251,127.38 -48.031,127.6 -46.27,127.6 -45.098,128.772 -45.098,131.124 -45.573,131.599 USB101.A5@-45.573,131.934
USB_CC2: R89.2 U16.5 U16.6 USB101.B5 | length 14.3
  Top Signal w0.152: R89.2@-46.766,126.53 -46.766,127.113 -46.609,127.27 -46.151,127.27 -44.598,128.823 v1@-44.598,130.75
  Top Signal w0.2: v4(-46.987,132.947) -46.846,133.088 USB101.B5@-46.846,133.734
  GND w0.2: v4(-46.987,132.947) -47.708,132.947 -48.793,131.862 -48.793,130.709 -48.292,130.208 -45.192,130.208 v1(-44.596,130.803)
USB_D_N: R103.1 U16.1 U16.10 USB101.A7 USB101.B7 | length 18.1
  Top Signal w0.27: v1(-46.702,128.816) -46.596,128.922 USB101.A7@-46.596,132.134 ; USB101.B7@-45.846,133.734 -45.846,133.166 v4(-45.759,133.079) ; v1(-45.449,123.481) -45.3,123.333 -44.865,123.333 R103.1@-44.506,123.692
  Bottom Signal w0.27: v1(-46.702,128.816) -46.554,128.964 -46.554,129.103 -46.742,129.29 -47.132,129.29 -47.33,129.092 -47.33,123.814 -46.839,123.323 -45.623,123.323 ; v4(-46.664,131.357) -46.563,131.458 -46.563,131.845 -46.121,132.287 -45.292,132.287 -45.106,132.473 -45.106,133.279 -45.289,133.462 -45.752,133.462 -45.861,133.353 -45.861,133.181 v4(-45.759,133.079) ; v1@-45.607,123.323 v1(-45.449,123.481)
USB_D_P: R104.1 U16.2 U16.9 USB101.A6 USB101.B6 | length 21.6
  Top Signal w0.2: v4(-46.366,133.091) v4@-46.346,133.111
  Top Signal w0.27: v4@-46.346,133.111 USB101.B6@-46.346,133.734 ; USB101.A6@-46.096,132.134 -46.096,131.357 -46.096,128.938 v1(-45.987,128.829) ; v1(-45.484,122.764) -45.335,122.913 -44.903,122.913 R104.1@-44.506,122.515
  Bottom Signal w0.27: v4(-46.366,133.091) -46.281,133.176 -46.281,133.527 -45.926,133.882 -45.115,133.882 -44.686,133.453 -44.686,132.299 -45.118,131.867 -45.947,131.867 -46.143,131.671 -46.143,131.458 v4(-46.042,131.357) ; v1(-45.987,128.829) -46.134,128.977 -46.134,129.276 -46.568,129.71 -47.306,129.71 -47.75,129.266 -47.75,123.64 -47.013,122.903 -45.623,122.903 v1(-45.484,122.764)
USB_GND: C101.1 C105.1 C106.1 JP1.3 LED7.1 R88.1 R89.1 R100.1 U3.2 U3.8 U16.3@-45.598,129.449 U16.8@-45.598,130.284 USB101.1 USB101.2 USB101.3 USB101.4 USB101.A1 USB101.A12 USB101.B1 USB101.B12 | length 33.5
  Top Signal w0.3: v1(-50.306,130.219) -49.618,130.219 R100.1@-49.588,130.189 ; C101.1@-49.49,128.863 -49.49,131.181 -49.096,131.575 USB101.A12@-49.096,132.134 -49.096,132.933 -48.846,133.183 USB101.B1@-48.846,133.734 ; U16.8@-45.598,130.363 -45.577,130.384 U16.8@-45.593,130.4 ; U16.3@-45.593,129.511 v1@-45.593,130.82 ; C106.1@-43.643,128.152 C106.1@-43.587,128.208 ; USB101.B12@-43.346,133.734 -43.346,133.045 -43.596,132.795 USB101.A1@-43.596,132.134 v1(-43.165,132.134)
  Top Signal w0.5: v1(-44.178,128.152) C106.1@-43.643,128.152 ; C105.1@-43.623,128.922 -43.493,128.792 U3.2@-41.39,128.792
  Top Signal w0.762: LED7.1@-53.137,124.953 JP1.3@-53.137,121.336 -52.56,120.759 -49.023,120.759 -46.789,120.759 ; -48.251,121.531 R88.1@-48.251,124.814 R89.1@-46.703,124.814 -45.461,124.814 ; v3@-46.313,120.283 -41.39,120.283
  other v1: -42.93,120.23 -39.574,120.256 -54.481,120.394 -49.814,122.638 -51.74,123.367 -57.197,123.776 -44.049,124.578 -39.561,124.731 -49.581,124.827 -54.365,124.912 -49.639,126.461 -45.251,126.658 -56.529,126.736 -39.614,127.994 -54.542,128.095 -42.837,128.775 -57.256,129.379 -52.061,129.437 -45.557,130.82 -53.345,130.926 -49.502,130.923 -42.251,131.261 -39.534,131.602 -39.513,133.786 -57.256,134.515 -53.754,138.542
  other v3: -46.014,120.281 -52.075,120.745 -48.196,122.16 -53.141,123.714 -45.461,125.703
VDD: C9.2 C10.2 C11.2 C12.2 C111.2 C112.2 JP4.1 TP1.1 U1.4 U1.71 U1.87 | length 31.8
  Top Signal w0.3: U1.4@-31.403,72.846 -30.481,71.923 v1(-30.481,71.921) v1@-30.546,71.921 ; U1.71@-21.009,61.744 -20.09,60.825 v1(-19.991,60.825)
  Top Signal w0.305: v1(-24.56,67.442) -24.275,67.728 -24.275,68.52 U1.87@-23.484,69.31
  Top Signal w0.5: v1(-19.991,60.825) -19.884,60.718 -19.325,60.718 -13.304,66.738 v2(-11.901,66.738)
  Bottom Signal w0.5: v1(-30.481,71.921) -30.481,71.735 C10.2@-30.195,71.449 ; C10.2@-30.193,71.452 v1@-29.67,70.929 ; v1(-24.827,65.946) C11.2@-24.007,66.767 -24.56,67.32 v1(-24.56,67.442) ; v1(-24.075,64.225) -24.075,64.229 C9.2@-23.59,64.714 ; v1@-22.706,63.898 v1(-22.706,63.863) C12.2@-22.264,63.421 -19.991,61.147 v1(-19.991,60.825) ; TP1.1@-12.574,68.785 -11.901,68.112 v2(-11.901,66.738) C111.2@-10.912,66.738 ; C111.2@-10.859,66.686 -10.856,66.689 C112.2@-9.17,66.689 JP4.1@-6.351,66.689
  other v1: -29.668,70.931
VDDA: C14.2 C15.1 L2.2 TP3.1 U1.34 | length 8.5
  Top Signal w0.3: U1.34@-36,60.33 -35.127,61.203 v1(-34.461,61.203)
  Bottom Signal w0.5: L2.2@-37.475,58.282 -37.475,57.833 TP3.1@-36.146,56.504 ; C15.1@-36.142,59.46 -36.142,59.52 -35.29,60.372 v1(-34.461,61.203)
  Bottom Signal w0.8: L2.2@-37.475,58.282 -37.321,58.282 C15.1@-36.142,59.46
VDDIO: C19.2 C20.2 C21.2 C22.2 L3.2 TP2.1 U1.3 U1.70 U1.88 | length 15.5
  Top Signal w0.3: U1.3@-31.05,73.199 -30.331,72.48 -29.888,72.48 v1(-29.617,72.21) ; v1(-24.802,68.143) -24.802,68.699 U1.88@-23.837,69.664 ; v1(-22.459,62.269) -22.241,62.269 U1.70@-21.363,61.391
  PWR w0.5: -19.838,63.844 -18.247,63.844 -17.705,64.386 TP2.1@-17.705,64.632
  Bottom Signal w0.5: v1(-29.617,72.21) -29.304,72.522 C22.2@-29.304,72.595 -27.851,71.141 L3.2@-27.629,71.141 ; C19.2@-26.168,69.848 -25.087,68.768 C20.2@-25.087,68.643 -24.802,68.358 v1(-24.802,68.143) ; v1(-22.459,62.269) -22.241,62.269 C21.2@-21.995,62.024
  Bottom Signal w0.762: L3.2@-27.629,71.274 v1(-26.752,70.397) C19.2@-26.168,69.848
  other v1: -28.754,71.718
  other v2: -25.477,69.178
XDS_D_N: R1.2 U2.93 | length 28
  Top Signal w0.27: R1.2@-28.303,123.759 -28.17,123.759 -27.713,123.303 -27.441,123.303 v1(-27.298,123.446) ; v1@-12.321,129.154 -12.524,128.951 -12.838,128.951 -13.061,129.174 -13.061,132.094 -11.875,133.28 U2.93@-8.198,133.28
  Bottom Signal w0.2: v1(-27.298,123.446) -27.298,123.389 -27.267,123.358 -27.238,123.387 v1@-27.179,123.446
  Bottom Signal w0.27: v1(-27.298,123.446) -27.238,123.387 -27.182,123.331 -25.738,123.331 -20.105,128.964 -12.471,128.964 v1(-12.361,129.074)
XDS_D_P: R2.2 U2.94 | length 29.2
  Top Signal w0.27: R2.2@-28.303,122.426 -28.188,122.426 -27.731,122.883 -27.357,122.883 v1@-27.271,122.796 ; v1@-12.301,128.374 -12.458,128.531 -13.012,128.531 -13.481,129 -13.481,132.268 -12.049,133.7 U2.94@-8.177,133.7
  Bottom Signal w0.27: v1@-27.271,122.796 -27.156,122.911 -25.564,122.911 -19.931,128.544 -12.481,128.544 v1(-12.361,128.424)
  other v1: -27.298,122.796
XDS_RESET_OUT: J102.10 R57.1 U2.40 U5.1 | length 26.4
  Top Signal w0.127: R57.1@-9.023,111.438 R57.1@-8.743,111.438
  Top Signal w0.2: U5.1@-25.445,113.32 -25.445,113.617 -25.193,113.869 -22.808,113.869 -22.5,114.177 -11.762,114.177 R57.1@-9.023,111.438 ; U2.40@-18.636,120.584 -18.636,119.009 -17.986,118.359 -16.803,118.359 -16.379,117.935 J102.10@-16.379,116.349 -16.379,114.184
XDS_RXD: J101.3 J102.14 U2.33 U5.5 | length 33.3
  Top Signal w0.127: J101.3@-27.433,109.5 J101.3@-27.433,109.869
  Top Signal w0.2: J101.3@-27.433,109.5 -27.433,109.487 -26.577,108.631 -23.948,108.631 -23.524,109.055 -23.524,112.044 -24.3,112.82 U5.5@-24.87,112.82 ; v1@-21.61,119.533 -21.436,119.707 U2.33@-21.436,120.584 ; v1@-17.099,119.382 -15.132,119.382 -13.839,118.089 J102.14@-13.839,116.349 -13.863,116.325 v1(-13.863,114.757)
  Bottom Signal w0.2: v1(-23.54,111.353) -22.592,112.301 -16.319,112.301 v1(-13.863,114.757) ; v1(-21.519,119.563) -21.334,119.378 v1(-17.099,119.378)
XDS_TCK_SWDCLK: J101.7 J102.4 U2.35 U4.1 | length 28.5
  Top Signal w0.2: U4.1@-33.154,113.654 -32.872,113.654 v1(-32.513,113.295) J101.7@-32.513,109.869 ; U2.35@-20.636,120.584 -20.636,121.364 -20.919,121.647 -21.818,121.647 -22.889,120.576 -22.889,115.191 -22.315,114.617 -20.385,114.617 -20.189,114.813 J102.4@-20.189,116.349
  Bottom Signal w0.2: v1(-32.513,113.295) -31.14,113.295 -28.5,115.935 v1(-22.903,115.935)
XDS_TDI: J101.11 J102.8 U2.38 U4.5 | length 32.3
  Top Signal w0.2: J101.11@-37.593,109.869 -37.593,109.726 -36.452,108.585 -34.325,108.585 -33.669,109.241 U4.5@-33.669,113.035 ; U2.38@-19.436,120.584 -19.436,118.871 -18.57,118.005 -17.776,118.005 -17.649,117.878 J102.8@-17.649,116.349
  Bottom Signal w0.2: v1(-33.678,111.98) -33.678,113.211 -29.527,117.362 -19.534,117.362 v1(-18.704,118.192)
XDS_TDO_SWO: J101.9 J102.6 U2.37 U4.4 | length 25.6
  Top Signal w0.2: J101.9@-35.053,109.869 -35.053,110.875 -34.185,111.743 U4.4@-34.185,113.019 ; U2.37@-19.836,120.584 -19.836,118.494 -18.919,117.577 J102.6@-18.919,116.349
  Bottom Signal w0.2: v1(-34.218,112.539) -34.218,113.402 -29.741,117.879 -19.895,117.879 v1(-19.582,118.192)
XDS_TMS_SWDIO: J101.5 J102.2 U2.36 U4.2 | length 23.3
  Top Signal w0.2: U4.2@-33.654,113.679 -33.654,113.976 -33.379,114.251 -31.078,114.251 -29.973,113.146 J101.5@-29.973,109.869 ; v1(-22.114,116.839) -21.539,116.839 J102.2@-21.459,116.919 ; J102.2@-21.459,116.349 J102.2@-21.459,116.919 ; U2.36@-20.236,120.584 -20.236,118.924 -21.459,117.701 J102.2@-21.459,116.919
  Bottom Signal w0.2: v1(-31.061,114.255) -28.477,116.839 v1(-22.114,116.839)
XDS_TXD: J101.1 J102.12 U2.34 U5.4 | length 25.5
  Top Signal w0.127: U5.4@-24.893,112.234 U5.4@-24.756,112.371
  Top Signal w0.2: J101.1@-24.893,109.869 U5.4@-24.893,112.234 ; v1(-21.581,118.802) -21.036,119.347 U2.34@-21.036,120.584 ; v1@-17.729,118.82 -15.872,118.82 -15.109,118.057 J102.12@-15.109,116.349 -15.096,116.336 v1(-15.096,114.757)
  Bottom Signal w0.2: v1(-24.902,111.872) -24,112.774 -17.079,112.774 v1(-15.096,114.757) ; v1@-21.403,118.891 v1(-17.692,118.891)
XRSn: C17.1 J4/J2.16 J8/J6.56 R5.1 R11.1 S1.4 U1.2 | length 134.1
  Top Signal w0.127: v1(-31.363,85.815) -31.363,74.22 U1.2@-30.696,73.553 ; v1(-26.471,85.815) -25.137,87.149 -19.977,87.149 -18.873,88.254 v1(-17.097,88.254) ; R5.1@-7.658,107.301 -7.686,107.329 R5.1@-7.486,107.329 ; S1.4@-3.749,110.699 -3.749,109.886 -6.306,107.329 R5.1@-7.486,107.329 ; v1@-2.311,28.582 -2.312,28.583 -2.312,43.112 -2.312,84.158 -4.591,86.437 -4.591,90.329 J4/J2.16@-6.351,92.089 -7.65,93.388 -7.65,107.165 R5.1@-7.486,107.329
  Bottom Signal w0.127: R11.1@-29.86,85.114 C17.1@-31.354,85.114 -31.363,85.123 v1(-31.363,85.815) v1(-26.471,85.815) ; v1(-17.097,88.254) v1(-4.589,88.254) ; J8/J6.56@-6.351,28.589 v1(-2.311,28.589) ; J4/J2.16@-6.351,91.391 J4/J2.16@-6.351,92.089
XTAL_X1: C42.1 R33.2 R106.2 | length 4.2
  Top Signal w0.152: R33.2@-15.501,59.797 R33.2@-15.501,60.21 -14.819,59.528 R106.2@-13.591,59.528 -12.47,60.648 C42.1@-12.465,60.648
